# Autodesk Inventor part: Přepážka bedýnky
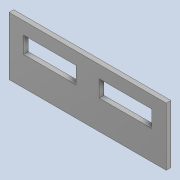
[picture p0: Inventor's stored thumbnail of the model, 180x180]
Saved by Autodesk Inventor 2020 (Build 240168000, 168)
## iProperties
Created: 2025-03
Part Number: Přepážka bedýnky
Material: Polypropylen
Document SubType Name: Modeling
Designer: doma
Density: 0.899 g/cm^3
Appearance: Hladká – středně šedá
Author: doma
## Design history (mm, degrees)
sketch "Náčrt1"
  geometry: L1 (-135, -50)-(135, -50); L2 (135, -50)-(135, 50); L3 (135, 50)-(-135, 50); L4 (-135, 50)-(-135, -50); L5 (-135, -50)-(135, 50); L6 (135, -50)-(-135, 50); L7 (-110, 0)-(-20, 0); L8 (-20, 0)-(-20, 28.708); L9 (-20, 28.708)-(-110, 28.708); L10 (-110, 28.708)-(-110, 0); L11 (20, 0)-(110, 0); L12 (110, 0)-(110, 28.708); L13 (110, 28.708)-(20, 28.708); L14 (20, 28.708)-(20, 0); L15 (0, -70)-(0, 70) reference; 1 further point
  constraints: 28 end point, 6 parallel, 3 horizontal, 3 perpendicular, 2 midpoint, 2 point on line, 2 other
  dimensions: "d0" = 270 distance of L3.end L2.end; "d1" = 100 distance of L2.end L1.end; "d2" = 90 distance of L8.end L9.end; "d3" = 40 distance between parallel lines of L14 L8
extrude "Vysunutí1" new body sketch "Náčrt1" distance "d4" = 8; taper "d5" = 0 deg
node "Těleso1"
